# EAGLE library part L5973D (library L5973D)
2.5A switch step down switching regulator
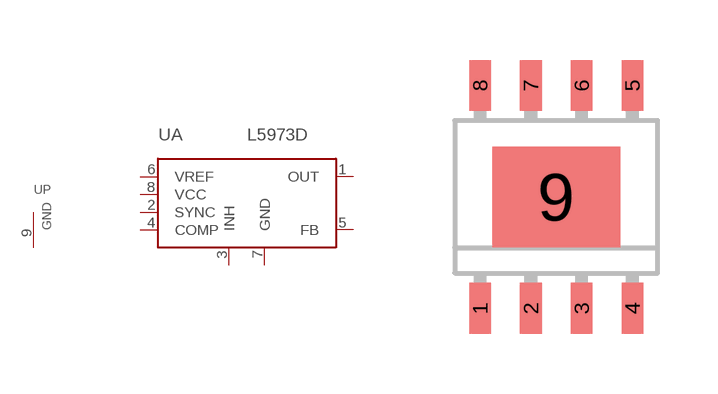
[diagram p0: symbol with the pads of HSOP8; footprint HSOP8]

Designator prefix U; gates A=L5973D P=GND

## L5973D  [HSOP8]
1  A:OUT  sup
2  A:SYNC
3  A:INH  in
4  A:COMP  out
5  A:FB  in
6  A:VREF  out
7  A:GND  pwr
8  A:VCC  sup
9  P:GND  pwr

## Footprint HSOP8 (pad centres in mm)
smd 0.54 x 1.27: 1 -1.905,-2.785; 2 -0.635,-2.785; 3 0.635,-2.785; 4 1.905,-2.785; 5 1.905,2.785; 6 0.635,2.785; 7 -0.635,2.785; 8 -1.905,2.785
smd 3.2 x 2.51: 9 0,0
